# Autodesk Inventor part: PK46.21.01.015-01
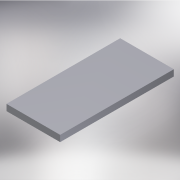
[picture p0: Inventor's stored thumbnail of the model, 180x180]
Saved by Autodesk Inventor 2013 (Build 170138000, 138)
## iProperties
Created: 2005-04
Part Number: PK46.21.01.015-01
Material: Steel, Mild
Document SubType Name: Modeling
Designer: salex
Manufacturer: Standard
Standards Organization: Custom
Density: 7.86 g/cm^3
Author: salex
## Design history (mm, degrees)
sketch "Эскиз1"
  geometry: L1 (0, 0)-(85, 0); L2 (85, 0)-(85, 180); L3 (85, 180)-(0, 180); L4 (0, 180)-(0, 0)
  constraints: 8 end point, 2 parallel, 1 horizontal, 1 perpendicular, 1 other
  dimensions: "d0" = 180 distance of L3.end L1.start; "d1" = 85 distance of L1.start L1.end
extrude "Выдавливание1" new body sketch "Эскиз1" distance "d2" = 10; taper "d3" = 0 deg
body "Solid1"
